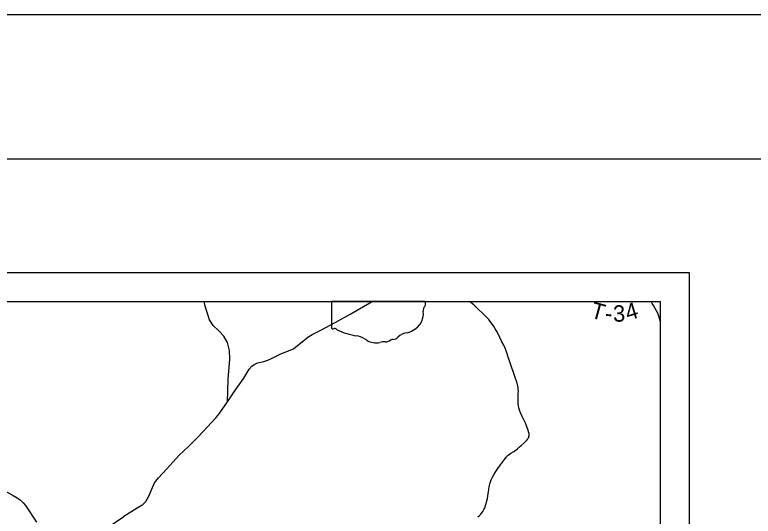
# Model space of a CAD drawing. Extents: x 0 to 34, y 0 to 22.
# Drawn here: x 6.535 to 9.099, y 20.26 to 22 of the extents above; entities that cross this region are included whole.
import ezdxf

# ---------------------------------------------------------------- set-up
doc = ezdxf.new("R2010")
doc.units = 0
for name, color, linetype in [('GM_X_County_Road', 7, 'Continuous'), ('GM_X_State_Location', 7, 'Continuous'), ('GM_X_State_Route', 7, 'Continuous'), ('GM_X_Township_Road', 7, 'Continuous'), ('GM_X_Township_Road_Text', 7, 'Continuous'), ('GM_X_Unincorporated_Text', 7, 'Continuous'), ('SH_Border', 7, 'Continuous'), ('SH_Cut_Line', 7, 'Continuous'), ('SH_Data', 7, 'Continuous')]:
    doc.layers.add(name, color=color, linetype=linetype)

msp = doc.modelspace()

# ---------------------------------------------------------------- linework, layer by layer
at = {"layer": 'GM_X_County_Road'}
for points in [[(6.0131, 20.6084), (6.0344, 20.5971), (6.1966, 20.51), (6.3358, 20.4355), (6.4522, 20.373), (6.5292, 20.3317), (6.543, 20.3236), (6.5502, 20.3186)], [(6.5502, 20.3186), (6.5533, 20.3164), (6.5634, 20.3062), (6.5719, 20.2968), (6.6102, 20.2392)]]:
    msp.add_lwpolyline(points, dxfattribs=at)
at = {"layer": 'GM_X_State_Route'}
for points in [[(6.9136, 20.2597), (6.959, 20.2888), (6.9787, 20.3009), (6.9891, 20.3108), (6.9992, 20.3269), (7.0129, 20.3596), (7.0194, 20.3756), (7.0332, 20.3928), (7.0621, 20.4246), (7.1043, 20.4705), (7.1392, 20.5033), (7.1737, 20.5381), (7.233, 20.6015), (7.2392, 20.6091), (7.247, 20.6187), (7.2729, 20.6567), (7.2962, 20.6914), (7.3303, 20.7392), (7.3486, 20.7699), (7.3577, 20.7805), (7.3658, 20.7868), (7.3769, 20.7916), (7.3996, 20.7966), (7.4139, 20.8014), (7.4282, 20.8077), (7.458, 20.8237), (7.5027, 20.8412), (7.516, 20.8522), (7.532, 20.865), (7.5523, 20.8809), (7.5676, 20.8906), (7.5979, 20.9056), (7.6466, 20.932), (7.7017, 20.9623), (7.7681, 21.0005), (7.7767, 21.0054)], [(6.7665, 20.065), (6.7685, 20.0693), (6.7715, 20.0755), (6.7787, 20.0904), (6.7951, 20.125), (6.815, 20.1683), (6.8266, 20.1868), (6.8388, 20.2031), (6.8496, 20.2144), (6.859, 20.2223), (6.9128, 20.2592), (6.9136, 20.2597)]]:
    msp.add_lwpolyline(points, dxfattribs=at)
at = {"layer": 'GM_X_Township_Road'}
for points in [[(7.2729, 20.6567), (7.2761, 20.7347), (7.2809, 20.8047), (7.2799, 20.8347), (7.2736, 20.8624), (7.2608, 20.8843), (7.2432, 20.9028), (7.2237, 20.9213), (7.2106, 20.9418), (7.1962, 20.9892), (7.1926, 21.0054)], [(8.1427, 20.2579), (8.1486, 20.2625), (8.1526, 20.2668), (8.1564, 20.2711), (8.16, 20.276), (8.1636, 20.2826), (8.1666, 20.2892), (8.1707, 20.3004), (8.176, 20.3209), (8.1788, 20.3372), (8.1805, 20.3519), (8.1819, 20.3619), (8.1852, 20.3758), (8.1892, 20.386), (8.1938, 20.3949), (8.1997, 20.4062), (8.2055, 20.4147), (8.2124, 20.4254), (8.2208, 20.4379), (8.2284, 20.4475), (8.2355, 20.4564), (8.2413, 20.4646), (8.248, 20.4714), (8.2566, 20.4788), (8.267, 20.4841), (8.28, 20.4935), (8.2874, 20.5004), (8.2928, 20.5054), (8.3034, 20.5147), (8.308, 20.5188), (8.3122, 20.5231), (8.3143, 20.5254), (8.3162, 20.5278), (8.3178, 20.5305), (8.3192, 20.5333), (8.3201, 20.5364), (8.3207, 20.5397), (8.3208, 20.5431), (8.3204, 20.5467), (8.3186, 20.5525), (8.3169, 20.5581), (8.3125, 20.5702), (8.309, 20.58), (8.3034, 20.5924), (8.2968, 20.6056), (8.2904, 20.6189), (8.2868, 20.6278), (8.2846, 20.6356), (8.2835, 20.6427), (8.283, 20.6488), (8.283, 20.6567), (8.2831, 20.6844), (8.2833, 20.6937), (8.2831, 20.6999), (8.2824, 20.7061), (8.2812, 20.7121), (8.2787, 20.721), (8.2711, 20.7446), (8.2552, 20.7917), (8.2484, 20.8122), (8.244, 20.8238), (8.2406, 20.8336), (8.237, 20.8433), (8.2324, 20.853), (8.2251, 20.8672), (8.2189, 20.8798), (8.2092, 20.8991), (8.2033, 20.9099), (8.1966, 20.9203), (8.1859, 20.9355), (8.1804, 20.9428), (8.1646, 20.959), (8.1381, 20.984), (8.1284, 20.9929), (8.1137, 21.0054)], [(8.7763, 20.937), (8.7746, 20.9411), (8.7718, 20.9511), (8.7676, 20.9647), (8.7629, 20.973), (8.7586, 20.9809), (8.7521, 20.9906), (8.7481, 20.9977), (8.7449, 21.0054)]]:
    msp.add_lwpolyline(points, dxfattribs=at)
at = {"layer": 'GM_X_Unincorporated_Text'}
msp.add_lwpolyline([(7.9592, 21.0054), (7.6342, 21.0054), (7.6342, 20.914)], dxfattribs=at)
for centre, major_axis, start_param, end_param in [((7.9268, 20.9969), (0.0341, 0), 5.934695, 6.601432), ((7.9769, 20.974), (0.0248, 0), 2.387724, 3.262537), ((7.866, 20.9607), (0.0874, 0), 5.101753, 6.440018), ((7.638, 20.9136), (0.00385, 0), 2.993084, 4.5083), ((7.6386, 20.934), (0.0294, 0), 4.665946, 4.897461), ((7.6446, 20.9024), (0.0106, 0), 0.519207, 1.627899), ((7.7784, 21.0822), (0.2524, 0), 4.195997, 4.488961), ((7.7032, 20.8241), (0.079, 0), 0.823519, 1.323587), ((7.8422, 20.8946), (0.0282, 0), 4.937069, 5.64225), ((7.9028, 20.8578), (0.0479, 0), 1.647645, 2.488434), ((7.7886, 20.9015), (0.0501, 0), 4.026481, 4.996735), ((7.8176, 20.8323), (0.0412, 0), 1.495662, 1.94098), ((7.8212, 20.8865), (0.0267, 0), 4.691044, 5.507374), ((7.8454, 20.8671), (0.00752, 0), 1.147584, 2.315152)]:
    msp.add_ellipse(centre, major_axis=major_axis, ratio=0.8, start_param=start_param, end_param=end_param, dxfattribs=at)
at = {"layer": 'SH_Border'}
msp.add_lwpolyline([(1.5, 21.5), (33.5, 21.5), (33.5, 0.5), (1.5, 0.5)], close=True, dxfattribs=at)
at = {"layer": 'SH_Cut_Line'}
msp.add_lwpolyline([(0, 0), (34, 0), (34, 22), (0, 22)], close=True, dxfattribs=at)
at = {"layer": 'SH_Data'}
for p, q in [((1.8763, 21.1054), (8.8763, 21.1054)), ((8.8763, 21.1054), (8.8763, 14.1054)), ((1.9763, 21.0054), (8.7763, 21.0054)), ((8.7763, 21.0054), (8.7763, 14.2054))]:
    msp.add_line(p, q, dxfattribs=at)

# ---------------------------------------------------------------- texts
at = {"layer": 'GM_X_State_Location'}
msp.add_text('595', height=0.000189, rotation=0, dxfattribs=at).set_placement((7.7284, 20.987))
for s in ['s', 'r']:
    msp.add_text(s, height=0.000189, dxfattribs=at).set_placement((7.7953, 21.0007))
at = {"layer": 'GM_X_Township_Road_Text'}
for s, rotation, p in [('T', 344.6145, (8.5305, 20.9499)), ('3', 1.5835, (8.6128, 20.9344)), ('4', 16.8225, (8.664, 20.938)), ('-', 355.1297, (8.5826, 20.9366))]:
    msp.add_text(s, height=0.0568, rotation=rotation, dxfattribs=at).set_placement(p)

doc.saveas('drawing.dxf')
